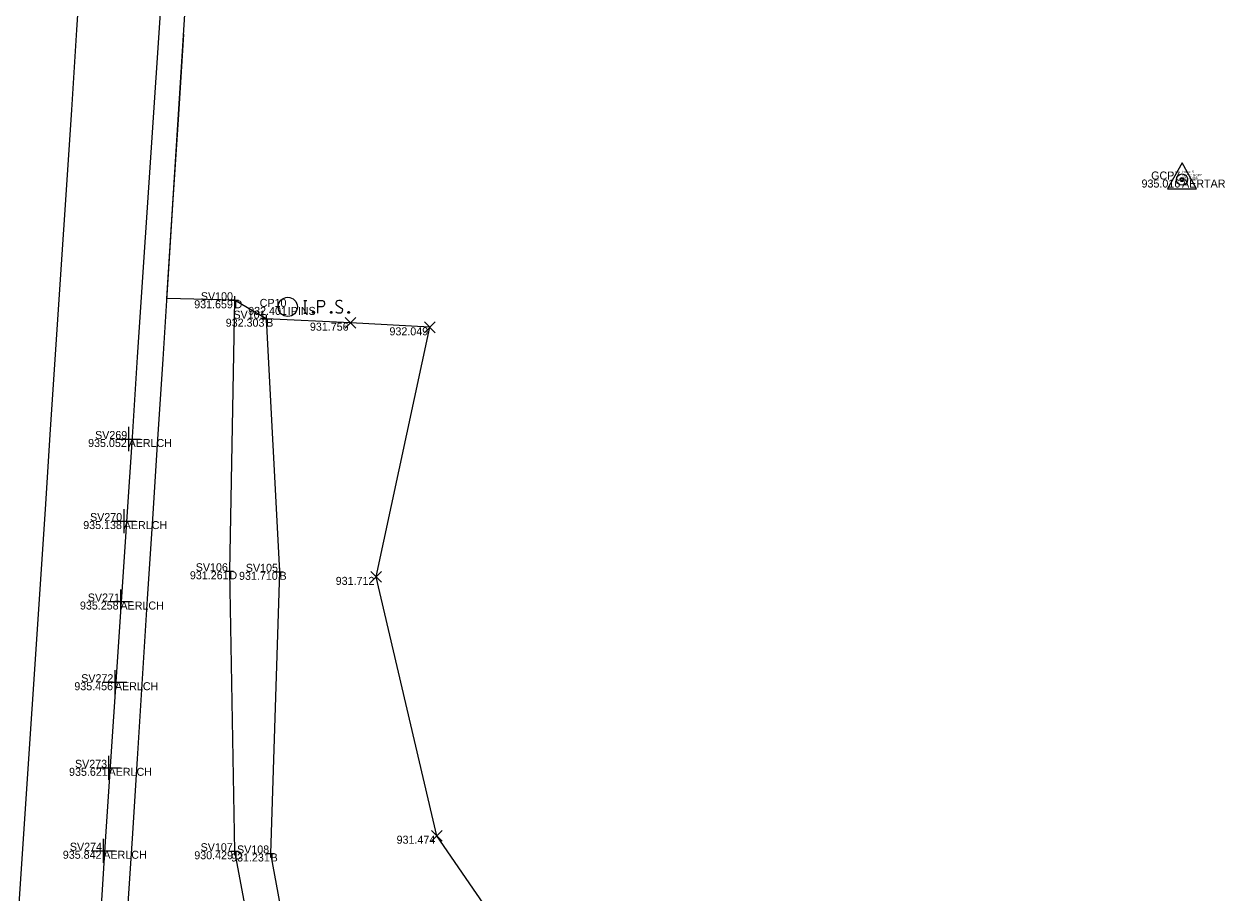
# Model space of a CAD drawing. Extents: x 1988835 to 1989144, y 657973 to 659339.
# Drawn here: x 1988993.8 to 1989143.9, y 658724.6 to 658833.1 of the extents above; entities that cross this region are included whole.
import ezdxf

# ---------------------------------------------------------------- set-up
doc = ezdxf.new("R2010")
doc.units = 0
for name, color, linetype in [('DR_X_Ditch', 7, 'Continuous'), ('DT_X_Terrain_Boundary', 7, 'Continuous'), ('PM_X_CL_Pass_Proh_Rt', 7, 'Continuous'), ('PV_X_EOP', 7, 'Continuous'), ('PV_X_Shoulder_Aggregate', 7, 'Continuous'), ('SV_P_Mon_Cells_Set', 7, 'Continuous'), ('SV_X_Break_Lines', 7, 'Continuous'), ('SV_X_LiDAR_Check_Spots', 7, 'Continuous'), ('SV_X_Random_Point', 7, 'Continuous'), ('SV_X_Shot_Marker', 7, 'Continuous'), ('SV_X_Text_Comment', 7, 'Continuous'), ('SV_X_Text_Elevation', 7, 'Continuous'), ('UT_X_Telecom', 7, 'Continuous'), ('UT_X_Telecom_Cells', 7, 'Continuous')]:
    doc.layers.add(name, color=color, linetype=linetype)

msp = doc.modelspace()

# ---------------------------------------------------------------- linework, layer by layer
at = {"layer": 'DR_X_Ditch'}
msp.add_lwpolyline([(1989020.1, 658798.63), (1989019.46, 658764.78), (1989020.11, 658729.81), (1989025.53, 658700.77), (1989026.35, 658684.97)], dxfattribs=at)
at = {"layer": 'DT_X_Terrain_Boundary'}
msp.add_lwpolyline([(1988964.62, 658494.73), (1988978, 658493.13), (1988991.98, 658491.88), (1988996.56, 658563.26), (1989005.48, 658554.05), (1989016.29, 658553.87), (1989055.69, 658591.48), (1989072.05, 658632.76), (1989075.24, 658671.01), (1989070.71, 658691.89), (1989069.57, 658706.91), (1989055.31, 658717.34), (1989045.38, 658731.75), (1989037.8, 658764.08), (1989044.5, 658795.25), (1989034.59, 658795.83), (1989024.05, 658796.33), (1989020.1, 658798.63), (1989011.65, 658798.86), (1989014.02, 658836.36)], dxfattribs=at)
at = {"layer": 'PM_X_CL_Pass_Proh_Rt'}
msp.add_lwpolyline([(1988985.91, 658612.87), (1988986.57, 658622.85), (1988987.23, 658632.83), (1988987.89, 658642.8), (1988988.55, 658652.78), (1988989.21, 658662.76), (1988989.87, 658672.74), (1988990.52, 658682.72), (1988991.18, 658692.7), (1988991.84, 658702.67), (1988992.5, 658712.65), (1988993.16, 658722.63), (1988993.82, 658732.61), (1988994.48, 658742.59), (1988995.14, 658752.57), (1988995.8, 658762.54), (1988996.46, 658772.52), (1988997.12, 658782.5), (1988997.78, 658792.48), (1988998.44, 658802.46), (1988999.09, 658812.43), (1988999.75, 658822.41), (1989000.41, 658832.39), (1989001.07, 658842.37)], dxfattribs=at)
at = {"layer": 'PV_X_EOP'}
msp.add_lwpolyline([(1988996.1, 658611.92), (1988996.76, 658621.89), (1988997.42, 658631.87), (1988998.08, 658641.85), (1988998.74, 658651.83), (1988999.4, 658661.81), (1989000.06, 658671.78), (1989000.73, 658681.76), (1989001.39, 658691.74), (1989002.05, 658701.72), (1989002.71, 658711.7), (1989003.37, 658721.68), (1989004.03, 658731.65), (1989004.69, 658741.63), (1989005.35, 658751.61), (1989006.01, 658761.59), (1989006.67, 658771.57), (1989007.33, 658781.54), (1989007.99, 658791.52), (1989008.65, 658801.5), (1989009.31, 658811.48), (1989009.97, 658821.46), (1989010.63, 658831.43), (1989011.29, 658841.41)], dxfattribs=at)
at = {"layer": 'PV_X_Shoulder_Aggregate'}
msp.add_lwpolyline([(1988999.65, 658611.63), (1989000.29, 658621.61), (1989000.93, 658631.59), (1989001.57, 658641.57), (1989002.21, 658651.55), (1989002.85, 658661.53), (1989003.49, 658671.51), (1989004.13, 658681.49), (1989004.77, 658691.47), (1989005.41, 658701.45), (1989006.05, 658711.43), (1989006.69, 658721.41), (1989007.33, 658731.39), (1989007.96, 658741.37), (1989008.6, 658751.35), (1989009.24, 658761.33), (1989009.88, 658771.31), (1989010.52, 658781.29), (1989011.16, 658791.27), (1989011.8, 658801.25), (1989012.44, 658811.22), (1989013.08, 658821.2), (1989013.72, 658831.18), (1989013.76, 658831.87)], dxfattribs=at)
at = {"layer": 'SV_P_Mon_Cells_Set'}
for points in [[(1989028.76, 658798.61), (1989029.12, 658798.61)], [(1989028.94, 658797.01), (1989028.94, 658798.61)], [(1989030.51, 658797.01), (1989030.51, 658798.61), (1989031.04, 658798.61), (1989031.09, 658798.59), (1989031.17, 658798.57), (1989031.2, 658798.54), (1989031.23, 658798.52), (1989031.28, 658798.46), (1989031.31, 658798.39), (1989031.33, 658798.29), (1989031.33, 658798.14), (1989031.32, 658798.09), (1989031.3, 658798.01), (1989031.26, 658797.93), (1989031.21, 658797.89), (1989031.18, 658797.86), (1989031.12, 658797.84), (1989031.04, 658797.83), (1989030.51, 658797.83)], [(1989033.52, 658798.49), (1989033.49, 658798.52), (1989033.46, 658798.54), (1989033.36, 658798.58), (1989033.24, 658798.61), (1989033.15, 658798.61), (1989033.12, 658798.61), (1989032.98, 658798.57), (1989032.85, 658798.49), (1989032.78, 658798.39), (1989032.76, 658798.29), (1989032.76, 658798.22), (1989032.78, 658798.12), (1989032.87, 658798.03), (1989033.47, 658797.65), (1989033.53, 658797.6), (1989033.55, 658797.55), (1989033.57, 658797.47), (1989033.57, 658797.4), (1989033.56, 658797.32), (1989033.55, 658797.27), (1989033.53, 658797.21), (1989033.5, 658797.16), (1989033.48, 658797.12), (1989033.45, 658797.08), (1989033.42, 658797.06), (1989033.37, 658797.03), (1989033.34, 658797.02), (1989033.24, 658797.01), (1989033.09, 658797.01), (1989032.99, 658797.03), (1989032.84, 658797.12), (1989032.76, 658797.2)], [(1989028.76, 658797.01), (1989029.12, 658797.01)], [(1989029.9, 658797.22), (1989029.96, 658797.22), (1989029.99, 658797.2), (1989030.02, 658797.15), (1989030.02, 658797.08), (1989029.99, 658797.03), (1989029.96, 658797.01), (1989029.9, 658797.01), (1989029.87, 658797.03), (1989029.83, 658797.08), (1989029.83, 658797.15), (1989029.87, 658797.2), (1989029.9, 658797.22)], [(1989032.15, 658797.22), (1989032.2, 658797.22), (1989032.24, 658797.2), (1989032.27, 658797.15), (1989032.27, 658797.08), (1989032.24, 658797.03), (1989032.2, 658797.01), (1989032.15, 658797.01), (1989032.12, 658797.03), (1989032.08, 658797.08), (1989032.08, 658797.15), (1989032.12, 658797.2), (1989032.15, 658797.22)], [(1989034.33, 658797.22), (1989034.39, 658797.22), (1989034.42, 658797.2), (1989034.45, 658797.15), (1989034.45, 658797.08), (1989034.42, 658797.03), (1989034.39, 658797.01), (1989034.33, 658797.01), (1989034.3, 658797.03), (1989034.27, 658797.08), (1989034.27, 658797.15), (1989034.3, 658797.2), (1989034.33, 658797.22)]]:
    msp.add_lwpolyline(points, dxfattribs=at)
msp.add_circle((1989026.75, 658797.8), 1.2, dxfattribs=at)
at = {"layer": 'SV_X_Break_Lines'}
msp.add_lwpolyline([(1989024.05, 658796.33), (1989025.72, 658764.71), (1989024.61, 658729.53), (1989029.64, 658702.24), (1989031.3, 658688.11), (1989033.19, 658683.09), (1989043.4, 658678.4), (1989068.21, 658677.63)], dxfattribs=at)
at = {"layer": 'SV_X_LiDAR_Check_Spots'}
for p, q in [((1989006.86, 658782.8), (1989006.86, 658779.8)), ((1989005.36, 658781.3), (1989008.36, 658781.3)), ((1989006.86, 658781.3), (1989006.86, 658781.3)), ((1989006.25, 658772.55), (1989006.25, 658769.55)), ((1989004.75, 658771.05), (1989007.75, 658771.05)), ((1989006.25, 658771.05), (1989006.25, 658771.05)), ((1989005.84, 658762.5), (1989005.84, 658759.5)), ((1989004.34, 658761), (1989007.34, 658761)), ((1989005.84, 658761), (1989005.84, 658761)), ((1989005.15, 658752.42), (1989005.15, 658749.42)), ((1989003.65, 658750.92), (1989006.65, 658750.92)), ((1989005.15, 658750.92), (1989005.15, 658750.92)), ((1989004.36, 658741.73), (1989004.36, 658738.73)), ((1989002.86, 658740.23), (1989005.86, 658740.23)), ((1989004.36, 658740.23), (1989004.36, 658740.23)), ((1989003.7, 658731.37), (1989003.7, 658728.37)), ((1989002.2, 658729.87), (1989005.2, 658729.87)), ((1989003.7, 658729.87), (1989003.7, 658729.87))]:
    msp.add_line(p, q, dxfattribs=at)
at = {"layer": 'SV_X_Random_Point'}
for p, q in [((1989033.92, 658795.16), (1989035.26, 658796.49)), ((1989033.92, 658796.49), (1989035.26, 658795.16)), ((1989043.84, 658794.58), (1989045.17, 658795.92)), ((1989043.84, 658795.92), (1989045.17, 658794.58)), ((1989037.13, 658763.41), (1989038.47, 658764.75)), ((1989037.13, 658764.75), (1989038.47, 658763.41)), ((1989044.72, 658731.08), (1989046.05, 658732.41)), ((1989044.72, 658732.41), (1989046.05, 658731.08))]:
    msp.add_line(p, q, dxfattribs=at)
at = {"layer": 'SV_X_Shot_Marker'}
for p, q in [((1989019.6, 658798.63), (1989020.6, 658798.63)), ((1989020.1, 658799.13), (1989020.1, 658798.13)), ((1989020.1, 658798.63), (1989020.1, 658798.63)), ((1989024.05, 658796.83), (1989024.05, 658795.83)), ((1989023.55, 658796.33), (1989024.55, 658796.33)), ((1989024.05, 658796.33), (1989024.05, 658796.33)), ((1989019.46, 658765.28), (1989019.46, 658764.28)), ((1989025.72, 658765.21), (1989025.72, 658764.21)), ((1989018.96, 658764.78), (1989019.96, 658764.78)), ((1989019.46, 658764.78), (1989019.46, 658764.78)), ((1989025.22, 658764.71), (1989026.22, 658764.71)), ((1989025.72, 658764.71), (1989025.72, 658764.71)), ((1989019.61, 658729.81), (1989020.61, 658729.81)), ((1989020.11, 658730.31), (1989020.11, 658729.31)), ((1989020.11, 658729.81), (1989020.11, 658729.81)), ((1989024.11, 658729.53), (1989025.11, 658729.53)), ((1989024.61, 658730.03), (1989024.61, 658729.03)), ((1989024.61, 658729.53), (1989024.61, 658729.53))]:
    msp.add_line(p, q, dxfattribs=at)
at = {"layer": 'SV_X_Text_Elevation'}
msp.add_line((1989138.5, 658813.71), (1989138.5, 658813.71), dxfattribs=at)
msp.add_lwpolyline([(1989136.7, 658812.56), (1989140.3, 658812.56), (1989138.5, 658815.78)], close=True, dxfattribs=at)
for radius in [0.7, 0.16]:
    msp.add_circle((1989138.5, 658813.71), radius, dxfattribs=at)
at = {"layer": 'UT_X_Telecom'}
msp.add_line((1989138.5, 658813.71), (1989138.5, 658813.71), dxfattribs=at)
msp.add_circle((1989138.5, 658813.71), 0.25, dxfattribs=at)

# ---------------------------------------------------------------- texts
at = {"layer": 'SV_X_Text_Comment'}
for s, p in [('GCP7', (1989134.64, 658813.71)), ('SV100', (1989015.89, 658798.63)), ('CP10', (1989023.24, 658797.8)), ('SV101', (1989019.96, 658796.33)), ('SV269', (1989002.67, 658781.3)), ('SV270', (1989002.04, 658771.05)), ('SV106', (1989015.25, 658764.78)), ('SV105', (1989021.51, 658764.71)), ('SV271', (1989001.76, 658761)), ('SV272', (1989000.94, 658750.92)), ('SV273', (1989000.16, 658740.23)), ('SV274', (1988999.52, 658729.87)), ('SV107', (1989015.86, 658729.81)), ('SV108', (1989020.41, 658729.53))]:
    msp.add_text(s, height=1, dxfattribs=at).set_placement(p)
at = {"layer": 'UT_X_Telecom'}
for s, height, p in [('Index: 5', 0.3, (1989138.5, 658814.51)), ('ΔZ: -0.006', 0.3, (1989138.5, 658813.71)), ('AERTAR', 1, (1989138.5, 658812.71)), ('Name: GCP7', 0.3, (1989138.5, 658814.11)), ('D', 1, (1989020.1, 658797.63)), ('IPINS', 1, (1989026.75, 658796.8)), ('B', 1, (1989024.05, 658795.33)), ('AERLCH', 1, (1989006.86, 658780.3)), ('AERLCH', 1, (1989006.25, 658770.05)), ('D', 1, (1989019.46, 658763.78)), ('B', 1, (1989025.72, 658763.71)), ('AERLCH', 1, (1989005.84, 658760)), ('AERLCH', 1, (1989005.15, 658749.92)), ('AERLCH', 1, (1989004.36, 658739.23)), ('AERLCH', 1, (1989003.7, 658728.87)), ('D', 1, (1989020.11, 658728.81)), ('B', 1, (1989024.61, 658728.53))]:
    msp.add_text(s, height=height, dxfattribs=at).set_placement(p)
at = {"layer": 'UT_X_Telecom_Cells'}
for s, p in [('935.016', (1989133.44, 658812.71)), ('931.659', (1989015.06, 658797.63)), ('932.401', (1989021.81, 658796.8)), ('932.303', (1989019, 658795.33)), ('931.756', (1989029.52, 658794.83)), ('932.049', (1989039.46, 658794.25)), ('935.052', (1989001.8, 658780.3)), ('935.138', (1989001.19, 658770.05)), ('931.261', (1989014.52, 658763.78)), ('931.710', (1989020.66, 658763.71)), ('931.712', (1989032.74, 658763.08)), ('935.258', (1989000.78, 658760)), ('935.456', (1989000.08, 658749.92)), ('935.621', (1988999.42, 658739.23)), ('931.474', (1989040.35, 658730.75)), ('935.842', (1988998.64, 658728.87)), ('930.429', (1989015.07, 658728.81)), ('931.231', (1989019.67, 658728.53))]:
    msp.add_text(s, height=1, dxfattribs=at).set_placement(p)

doc.saveas('drawing.dxf')
